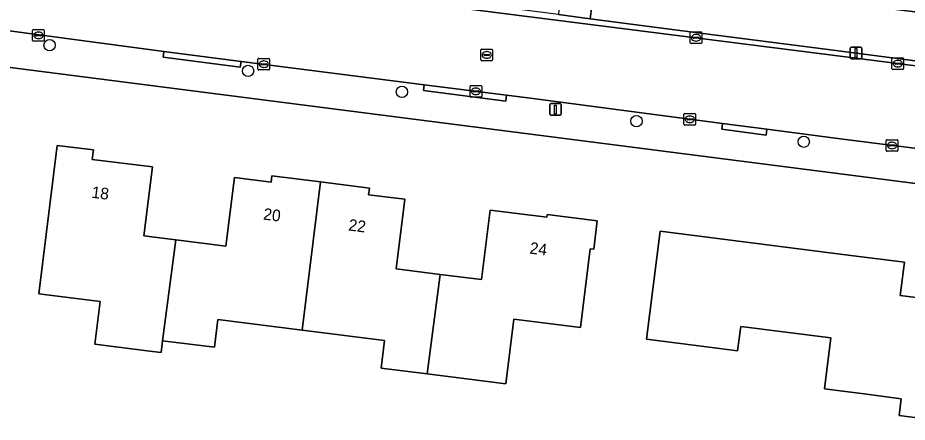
# Model space of a CAD drawing. Extents: x 162184 to 163154, y 385507 to 386516.
# Drawn here: x 162428.7 to 162505.3, y 386004.8 to 386039.6 of the extents above; entities that cross this region are included whole.
import ezdxf

# ---------------------------------------------------------------- set-up
doc = ezdxf.new("R2010")
doc.units = 0
for name, color, linetype in [('IMGEO_Boom', 7, 'Continuous'), ('IMGEO_Erf', 7, 'Continuous'), ('IMGEO_Groenvoorziening', 7, 'Continuous'), ('IMGEO_Kolk', 7, 'Continuous'), ('IMGEO_Lichtmast', 7, 'Continuous'), ('IMGEO_Pand', 7, 'Continuous'), ('IMGEO_Pand_nummerreeks', 7, 'Continuous'), ('IMGEO_Rijbaan_lokaal_open', 7, 'Continuous'), ('IMGEO_Rioolput', 7, 'Continuous'), ('IMGEO_Voetpad_open', 7, 'Continuous')]:
    doc.layers.add(name, color=color, linetype=linetype)

msp = doc.modelspace()

# ---------------------------------------------------------------- linework, layer by layer
at = {"layer": 'IMGEO_Boom'}
for centre in [(162431.465, 386037.28), (162448.562, 386035.061), (162461.812, 386033.263), (162482.006, 386030.738), (162496.412, 386028.965)]:
    msp.add_circle(centre, 0.489, dxfattribs=at)
at = {"layer": 'IMGEO_Erf'}
msp.add_lwpolyline([(162525.924, 386022.81), (162500, 386026.135), (162427.629, 386035.417), (162425.539, 386035.686)], dxfattribs=at)
for points in [[(162460.01, 386009.473), (162460.309, 386011.858), (162453.216, 386012.746), (162445.967, 386013.653), (162445.67, 386011.281), (162441.428, 386011.812), (162441.194, 386011.841), (162441.062, 386010.827), (162440.334, 386010.918), (162435.372, 386011.539), (162435.833, 386015.225), (162430.533, 386015.888), (162432.13, 386028.648), (162435.248, 386028.258), (162435.146, 386027.444), (162440.321, 386026.796), (162439.579, 386020.867), (162442.326, 386020.523), (162446.65, 386019.982), (162447.39, 386025.892), (162450.55, 386025.497), (162450.617, 386026.031), (162454.812, 386025.506), (162459.01, 386024.981), (162458.938, 386024.405), (162462.073, 386024.012), (162461.324, 386018.024), (162465.103, 386017.551), (162468.651, 386017.107), (162469.398, 386023.072), (162474.278, 386022.461), (162474.307, 386022.692), (162478.628, 386022.151), (162478.323, 386019.72), (162478.029, 386019.756), (162477.179, 386012.966), (162471.45, 386013.683), (162470.755, 386008.129), (162463.97, 386008.978)], [(162487.146, 386011.422), (162482.869, 386011.966), (162484.05, 386021.266), (162488.327, 386020.722), (162500, 386019.239), (162505.081, 386018.594), (162504.718, 386015.737), (162510.043, 386015.061), (162510.098, 386015.499), (162510.407, 386015.46), (162509.879, 386011.295), (162510.329, 386011.238), (162510.206, 386010.267), (162509.786, 386010.32), (162509.088, 386004.827), (162504.625, 386005.394), (162504.81, 386006.851), (162501.605, 386007.258), (162500, 386007.462), (162498.195, 386007.691), (162498.753, 386012.082), (162490.99, 386013.068), (162490.723, 386010.967)]]:
    msp.add_lwpolyline(points, close=True, dxfattribs=at)
at = {"layer": 'IMGEO_Groenvoorziening'}
msp.add_lwpolyline([(162478.556, 386043.58), (162478.063, 386039.785), (162478.033, 386039.554), (162487.53, 386038.32), (162498.29, 386036.923), (162500.92, 386036.604), (162519.499, 386034.169), (162519.545, 386034.527), (162520.029, 386038.411)], close=True, dxfattribs=at)
at = {"layer": 'IMGEO_Kolk'}
for p, q in [((162430.006, 386037.695), (162430.006, 386038.547)), ((162430.081, 386038.621), (162430.933, 386038.621)), ((162430.265, 386038.115), (162430.265, 386038.127)), ((162430.703, 386038.078), (162430.305, 386038.078)), ((162430.308, 386038.164), (162430.706, 386038.164)), ((162430.494, 386038.401), (162430.519, 386038.401)), ((162430.749, 386038.127), (162430.749, 386038.115)), ((162431.007, 386038.547), (162431.007, 386037.695)), ((162486.639, 386037.49), (162486.639, 386038.342)), ((162486.714, 386038.416), (162487.566, 386038.416)), ((162486.941, 386037.959), (162487.339, 386037.959)), ((162487.127, 386038.196), (162487.152, 386038.196)), ((162487.64, 386038.342), (162487.64, 386037.49)), ((162430.933, 386037.621), (162430.081, 386037.621)), ((162430.517, 386037.841), (162430.492, 386037.841)), ((162487.566, 386037.416), (162486.714, 386037.416)), ((162486.898, 386037.91), (162486.898, 386037.922)), ((162487.336, 386037.873), (162486.938, 386037.873)), ((162487.15, 386037.636), (162487.125, 386037.636)), ((162487.382, 386037.922), (162487.382, 386037.91)), ((162449.409, 386035.217), (162449.409, 386036.069)), ((162449.484, 386036.143), (162450.336, 386036.143)), ((162449.668, 386035.637), (162449.668, 386035.649)), ((162449.711, 386035.686), (162450.109, 386035.686)), ((162449.897, 386035.923), (162449.922, 386035.923)), ((162450.152, 386035.649), (162450.152, 386035.637)), ((162450.41, 386036.069), (162450.41, 386035.217)), ((162504.014, 386035.264), (162504.014, 386036.116)), ((162504.089, 386036.19), (162504.941, 386036.19)), ((162504.273, 386035.684), (162504.273, 386035.696)), ((162504.711, 386035.647), (162504.313, 386035.647)), ((162504.316, 386035.733), (162504.714, 386035.733)), ((162504.502, 386035.97), (162504.527, 386035.97)), ((162504.757, 386035.696), (162504.757, 386035.684)), ((162505.015, 386036.116), (162505.015, 386035.264)), ((162450.336, 386035.143), (162449.484, 386035.143)), ((162450.106, 386035.6), (162449.708, 386035.6)), ((162449.92, 386035.363), (162449.895, 386035.363)), ((162504.941, 386035.19), (162504.089, 386035.19)), ((162504.525, 386035.41), (162504.5, 386035.41)), ((162467.678, 386032.88), (162467.678, 386033.732)), ((162467.753, 386033.806), (162468.605, 386033.806)), ((162467.98, 386033.349), (162468.378, 386033.349)), ((162468.166, 386033.586), (162468.191, 386033.586)), ((162468.679, 386033.732), (162468.679, 386032.88)), ((162468.605, 386032.806), (162467.753, 386032.806)), ((162467.937, 386033.3), (162467.937, 386033.312)), ((162468.375, 386033.263), (162467.977, 386033.263)), ((162468.189, 386033.026), (162468.164, 386033.026)), ((162468.421, 386033.312), (162468.421, 386033.3)), ((162486.1, 386030.476), (162486.1, 386031.328)), ((162486.175, 386031.402), (162487.027, 386031.402)), ((162486.588, 386031.182), (162486.613, 386031.182)), ((162487.101, 386031.328), (162487.101, 386030.476)), ((162487.027, 386030.402), (162486.175, 386030.402)), ((162486.359, 386030.896), (162486.359, 386030.908)), ((162486.797, 386030.859), (162486.399, 386030.859)), ((162486.402, 386030.945), (162486.8, 386030.945)), ((162486.611, 386030.622), (162486.586, 386030.622)), ((162486.843, 386030.908), (162486.843, 386030.896)), ((162503.52, 386028.218), (162503.52, 386029.07)), ((162503.595, 386029.144), (162504.447, 386029.144)), ((162504.008, 386028.924), (162504.033, 386028.924)), ((162504.521, 386029.07), (162504.521, 386028.218)), ((162504.447, 386028.144), (162503.595, 386028.144)), ((162503.779, 386028.638), (162503.779, 386028.65)), ((162504.217, 386028.601), (162503.819, 386028.601)), ((162503.822, 386028.687), (162504.22, 386028.687)), ((162504.031, 386028.364), (162504.006, 386028.364)), ((162504.263, 386028.65), (162504.263, 386028.638))]:
    msp.add_line(p, q, dxfattribs=at)
for points in [[(162430.006, 386037.695), (162430.006, 386038.547)], [(162430.081, 386038.621), (162430.933, 386038.621)], [(162431.007, 386038.547), (162431.007, 386037.695)], [(162486.639, 386037.49), (162486.639, 386038.342)], [(162486.714, 386038.416), (162487.566, 386038.416)], [(162487.64, 386038.342), (162487.64, 386037.49)], [(162430.933, 386037.621), (162430.081, 386037.621)], [(162487.566, 386037.416), (162486.714, 386037.416)], [(162449.409, 386035.217), (162449.409, 386036.069)], [(162449.484, 386036.143), (162450.336, 386036.143)], [(162450.41, 386036.069), (162450.41, 386035.217)], [(162504.014, 386035.264), (162504.014, 386036.116)], [(162504.089, 386036.19), (162504.941, 386036.19)], [(162505.015, 386036.116), (162505.015, 386035.264)], [(162450.336, 386035.143), (162449.484, 386035.143)], [(162504.941, 386035.19), (162504.089, 386035.19)], [(162467.678, 386032.88), (162467.678, 386033.732)], [(162467.753, 386033.806), (162468.605, 386033.806)], [(162468.679, 386033.732), (162468.679, 386032.88)], [(162468.605, 386032.806), (162467.753, 386032.806)], [(162486.1, 386030.476), (162486.1, 386031.328)], [(162486.175, 386031.402), (162487.027, 386031.402)], [(162487.101, 386031.328), (162487.101, 386030.476)], [(162487.027, 386030.402), (162486.175, 386030.402)], [(162503.52, 386028.218), (162503.52, 386029.07)], [(162503.595, 386029.144), (162504.447, 386029.144)], [(162504.521, 386029.07), (162504.521, 386028.218)], [(162504.447, 386028.144), (162503.595, 386028.144)]]:
    msp.add_lwpolyline(points, dxfattribs=at)
for centre, radius, start, end in [((162430.083, 386038.545), 0.0765, 91.55205, 178.44795), ((162430.083, 386038.545), 0.0765, 91.55205, 178.44795), ((162430.305, 386038.124), 0.0403, 85.87752, 175.75265), ((162430.302, 386038.114), 0.0366, 178.93798, 274.71019), ((162430.706, 386038.121), 0.043, 264.86636, 352.45326), ((162430.71, 386038.126), 0.0386, 1.73085, 96.63898), ((162430.931, 386038.545), 0.0765, 1.55205, 88.44795), ((162430.931, 386038.545), 0.0765, 1.55205, 88.44795), ((162486.716, 386038.34), 0.0765, 91.55205, 178.44795), ((162486.716, 386038.34), 0.0765, 91.55205, 178.44795), ((162486.938, 386037.919), 0.0403, 85.87752, 175.75265), ((162487.343, 386037.921), 0.0386, 1.73085, 96.63898), ((162487.564, 386038.34), 0.0765, 1.55205, 88.44795), ((162487.564, 386038.34), 0.0765, 1.55205, 88.44795), ((162430.083, 386037.697), 0.0765, 181.55205, 268.44795), ((162430.083, 386037.697), 0.0765, 181.55205, 268.44795), ((162430.931, 386037.697), 0.0765, 271.55205, 358.44795), ((162430.931, 386037.697), 0.0765, 271.55205, 358.44795), ((162486.716, 386037.492), 0.0765, 181.55205, 268.44795), ((162486.716, 386037.492), 0.0765, 181.55205, 268.44795), ((162486.935, 386037.909), 0.0366, 178.93798, 274.71019), ((162487.339, 386037.916), 0.043, 264.86636, 352.45326), ((162487.564, 386037.492), 0.0765, 271.55205, 358.44795), ((162487.564, 386037.492), 0.0765, 271.55205, 358.44795), ((162449.486, 386036.067), 0.0765, 91.55205, 178.44795), ((162449.486, 386036.067), 0.0765, 91.55205, 178.44795), ((162449.708, 386035.646), 0.0403, 85.87752, 175.75265), ((162449.705, 386035.636), 0.0366, 178.93798, 274.71019), ((162450.109, 386035.643), 0.043, 264.86636, 352.45326), ((162450.113, 386035.648), 0.0386, 1.73085, 96.63898), ((162450.334, 386036.067), 0.0765, 1.55205, 88.44795), ((162450.334, 386036.067), 0.0765, 1.55205, 88.44795), ((162504.091, 386036.114), 0.0765, 91.55205, 178.44795), ((162504.091, 386036.114), 0.0765, 91.55205, 178.44795), ((162504.313, 386035.693), 0.0403, 85.87752, 175.75265), ((162504.31, 386035.683), 0.0366, 178.93798, 274.71019), ((162504.714, 386035.69), 0.043, 264.86636, 352.45326), ((162504.718, 386035.695), 0.0386, 1.73085, 96.63898), ((162504.939, 386036.114), 0.0765, 1.55205, 88.44795), ((162504.939, 386036.114), 0.0765, 1.55205, 88.44795), ((162449.486, 386035.219), 0.0765, 181.55205, 268.44795), ((162449.486, 386035.219), 0.0765, 181.55205, 268.44795), ((162450.334, 386035.219), 0.0765, 271.55205, 358.44795), ((162450.334, 386035.219), 0.0765, 271.55205, 358.44795), ((162504.091, 386035.266), 0.0765, 181.55205, 268.44795), ((162504.091, 386035.266), 0.0765, 181.55205, 268.44795), ((162504.939, 386035.266), 0.0765, 271.55205, 358.44795), ((162504.939, 386035.266), 0.0765, 271.55205, 358.44795), ((162467.755, 386033.73), 0.0765, 91.55205, 178.44795), ((162467.755, 386033.73), 0.0765, 91.55205, 178.44795), ((162467.977, 386033.309), 0.0403, 85.87752, 175.75265), ((162468.382, 386033.311), 0.0386, 1.73085, 96.63898), ((162468.603, 386033.73), 0.0765, 1.55205, 88.44795), ((162468.603, 386033.73), 0.0765, 1.55205, 88.44795), ((162467.755, 386032.882), 0.0765, 181.55205, 268.44795), ((162467.755, 386032.882), 0.0765, 181.55205, 268.44795), ((162467.974, 386033.299), 0.0366, 178.93798, 274.71019), ((162468.378, 386033.306), 0.043, 264.86636, 352.45326), ((162468.603, 386032.882), 0.0765, 271.55205, 358.44795), ((162468.603, 386032.882), 0.0765, 271.55205, 358.44795), ((162486.177, 386031.326), 0.0765, 91.55205, 178.44795), ((162486.177, 386031.326), 0.0765, 91.55205, 178.44795), ((162487.025, 386031.326), 0.0765, 1.55205, 88.44795), ((162487.025, 386031.326), 0.0765, 1.55205, 88.44795), ((162486.177, 386030.478), 0.0765, 181.55205, 268.44795), ((162486.177, 386030.478), 0.0765, 181.55205, 268.44795), ((162486.399, 386030.905), 0.0403, 85.87752, 175.75265), ((162486.396, 386030.895), 0.0366, 178.93798, 274.71019), ((162486.8, 386030.902), 0.043, 264.86636, 352.45326), ((162486.804, 386030.907), 0.0386, 1.73085, 96.63898), ((162487.025, 386030.478), 0.0765, 271.55205, 358.44795), ((162487.025, 386030.478), 0.0765, 271.55205, 358.44795), ((162503.597, 386029.068), 0.0765, 91.55205, 178.44795), ((162503.597, 386029.068), 0.0765, 91.55205, 178.44795), ((162504.445, 386029.068), 0.0765, 1.55205, 88.44795), ((162504.445, 386029.068), 0.0765, 1.55205, 88.44795), ((162503.597, 386028.22), 0.0765, 181.55205, 268.44795), ((162503.597, 386028.22), 0.0765, 181.55205, 268.44795), ((162503.819, 386028.647), 0.0403, 85.87752, 175.75265), ((162503.816, 386028.637), 0.0366, 178.93798, 274.71019), ((162504.22, 386028.644), 0.043, 264.86636, 352.45326), ((162504.224, 386028.649), 0.0386, 1.73085, 96.63898), ((162504.445, 386028.22), 0.0765, 271.55205, 358.44795), ((162504.445, 386028.22), 0.0765, 271.55205, 358.44795)]:
    msp.add_arc(centre, radius, start, end, dxfattribs=at)
for centre, major_axis, ratio, start_param, end_param in [((162430.493, 386038.121), (-0.387, 0.002), 0.722429, 4.712389, 7.853982), ((162430.518, 386038.121), (-0.39, 0.002), 0.717154, 1.570796, 4.712389), ((162487.126, 386037.916), (-0.387, 0.002), 0.722429, 4.712389, 7.853982), ((162487.151, 386037.916), (-0.39, 0.002), 0.717154, 1.570796, 4.712389), ((162449.896, 386035.643), (-0.387, 0.002), 0.722429, 4.712389, 7.853982), ((162449.921, 386035.643), (-0.39, 0.002), 0.717154, 1.570796, 4.712389), ((162504.501, 386035.69), (-0.387, 0.002), 0.722429, 4.712389, 7.853982), ((162504.526, 386035.69), (-0.39, 0.002), 0.717154, 1.570796, 4.712389), ((162468.165, 386033.306), (-0.387, 0.002), 0.722429, 4.712389, 7.853982), ((162468.19, 386033.306), (-0.39, 0.002), 0.717154, 1.570796, 4.712389), ((162486.587, 386030.902), (-0.387, 0.002), 0.722429, 4.712389, 7.853982), ((162486.612, 386030.902), (-0.39, 0.002), 0.717154, 1.570796, 4.712389), ((162504.007, 386028.644), (-0.387, 0.002), 0.722429, 4.712389, 7.853982), ((162504.032, 386028.644), (-0.39, 0.002), 0.717154, 1.570796, 4.712389)]:
    msp.add_ellipse(centre, major_axis=major_axis, ratio=ratio, start_param=start_param, end_param=end_param, dxfattribs=at)
at = {"layer": 'IMGEO_Lichtmast'}
for p, q in [((162500.425, 386036.204), (162500.425, 386037.004)), ((162500.425, 386037.004), (162500.425, 386036.204)), ((162500.525, 386037.104), (162501.315, 386037.104)), ((162501.315, 386037.104), (162500.525, 386037.104)), ((162501.415, 386037.004), (162501.415, 386036.204)), ((162501.415, 386036.204), (162501.415, 386037.004)), ((162501.315, 386036.104), (162500.525, 386036.104)), ((162500.525, 386036.104), (162501.315, 386036.104)), ((162474.536, 386031.352), (162474.536, 386032.152)), ((162474.536, 386032.152), (162474.536, 386031.352)), ((162474.636, 386032.252), (162475.426, 386032.252)), ((162475.426, 386032.252), (162474.636, 386032.252)), ((162475.526, 386032.152), (162475.526, 386031.352)), ((162475.526, 386031.352), (162475.526, 386032.152)), ((162475.426, 386031.252), (162474.636, 386031.252)), ((162474.636, 386031.252), (162475.426, 386031.252))]:
    msp.add_line(p, q, dxfattribs=at)
for points in [[(162500.845, 386036.979), (162500.995, 386036.979), (162500.995, 386036.229), (162500.845, 386036.229), (162500.845, 386036.979)], [(162474.956, 386032.127), (162475.106, 386032.127), (162475.106, 386031.377), (162474.956, 386031.377), (162474.956, 386032.127)]]:
    msp.add_lwpolyline(points, dxfattribs=at)
for centre, start, end in [((162500.525, 386037.004), 90, 180), ((162500.525, 386037.004), 90, 180), ((162501.315, 386037.004), 0, 90), ((162501.315, 386037.004), 360, 90), ((162500.525, 386036.204), 180, 270), ((162500.525, 386036.204), 180, 270), ((162501.315, 386036.204), 270, 0), ((162501.315, 386036.204), 270, 0), ((162474.636, 386032.152), 90, 180), ((162474.636, 386032.152), 90, 180), ((162475.426, 386032.152), 0, 90), ((162475.426, 386032.152), 360, 90), ((162474.636, 386031.352), 180, 270), ((162474.636, 386031.352), 180, 270), ((162475.426, 386031.352), 270, 0), ((162475.426, 386031.352), 270, 0)]:
    msp.add_arc(centre, 0.1, start, end, dxfattribs=at)
at = {"layer": 'IMGEO_Pand'}
for points in [[(162442.326, 386020.523), (162439.579, 386020.867), (162440.321, 386026.796), (162435.146, 386027.444), (162435.248, 386028.258), (162432.13, 386028.648), (162430.533, 386015.888), (162435.833, 386015.225), (162435.372, 386011.539), (162440.334, 386010.918), (162441.062, 386010.827), (162441.194, 386011.841)], [(162454.812, 386025.506), (162450.617, 386026.031), (162450.55, 386025.497), (162447.39, 386025.892), (162446.65, 386019.982), (162442.326, 386020.523), (162441.194, 386011.841), (162441.428, 386011.812), (162445.67, 386011.281), (162445.967, 386013.653), (162453.216, 386012.746)], [(162465.103, 386017.551), (162461.324, 386018.024), (162462.073, 386024.012), (162458.938, 386024.405), (162459.01, 386024.981), (162454.812, 386025.506), (162453.216, 386012.746), (162460.309, 386011.858), (162460.01, 386009.473), (162463.97, 386008.978)], [(162463.97, 386008.978), (162470.755, 386008.129), (162471.45, 386013.683), (162477.179, 386012.966), (162478.029, 386019.756), (162478.323, 386019.72), (162478.628, 386022.151), (162474.307, 386022.692), (162474.278, 386022.461), (162469.398, 386023.072), (162468.651, 386017.107), (162465.103, 386017.551)], [(162487.146, 386011.422), (162490.723, 386010.967), (162490.99, 386013.068), (162498.753, 386012.082), (162498.195, 386007.691), (162500, 386007.462), (162501.605, 386007.258), (162504.81, 386006.851), (162504.625, 386005.394), (162509.088, 386004.827), (162509.786, 386010.32), (162510.206, 386010.267), (162510.329, 386011.238), (162509.879, 386011.295), (162510.407, 386015.46), (162510.098, 386015.499), (162510.043, 386015.061), (162504.718, 386015.737), (162505.081, 386018.594), (162500, 386019.239), (162488.327, 386020.722), (162484.05, 386021.266), (162482.869, 386011.966)]]:
    msp.add_lwpolyline(points, close=True, dxfattribs=at)
at = {"layer": 'IMGEO_Rijbaan_lokaal_open'}
for points in [[(162500, 386036.267), (162458.097, 386041.609), (162453.274, 386042.224), (162441.857, 386043.741), (162416.511, 386047), (162403.455, 386048.678), (162392.654, 386050.067), (162370.437, 386052.921), (162333.146, 386057.71), (162331.957, 386057.856)], [(162411.465, 386040.722), (162441.318, 386036.733), (162447.955, 386035.886), (162463.723, 386033.874), (162470.821, 386032.968), (162472.666, 386032.732), (162489.419, 386030.537), (162493.24, 386030.037), (162500, 386029.151), (162526.463, 386025.819)], [(162530.454, 386032.366), (162500, 386036.267)]]:
    msp.add_lwpolyline(points, dxfattribs=at)
at = {"layer": 'IMGEO_Rioolput'}
for p, q in [((162468.612, 386036.016), (162468.612, 386036.868)), ((162468.687, 386036.942), (162469.539, 386036.942)), ((162468.871, 386036.436), (162468.871, 386036.448)), ((162468.914, 386036.485), (162469.312, 386036.485)), ((162469.1, 386036.722), (162469.125, 386036.722)), ((162469.355, 386036.448), (162469.355, 386036.436)), ((162469.613, 386036.868), (162469.613, 386036.016)), ((162469.539, 386035.942), (162468.687, 386035.942)), ((162469.309, 386036.399), (162468.911, 386036.399)), ((162469.123, 386036.162), (162469.098, 386036.162))]:
    msp.add_line(p, q, dxfattribs=at)
for points in [[(162468.612, 386036.016), (162468.612, 386036.868)], [(162468.687, 386036.942), (162469.539, 386036.942)], [(162469.613, 386036.868), (162469.613, 386036.016)], [(162469.539, 386035.942), (162468.687, 386035.942)]]:
    msp.add_lwpolyline(points, dxfattribs=at)
for centre, radius, start, end in [((162468.689, 386036.866), 0.0765, 91.55205, 178.44795), ((162468.689, 386036.866), 0.0765, 91.55205, 178.44795), ((162468.911, 386036.445), 0.0403, 85.87752, 175.75265), ((162468.908, 386036.435), 0.0366, 178.93798, 274.71019), ((162469.312, 386036.442), 0.043, 264.86636, 352.45326), ((162469.316, 386036.447), 0.0386, 1.73085, 96.63898), ((162469.537, 386036.866), 0.0765, 1.55205, 88.44795), ((162469.537, 386036.866), 0.0765, 1.55205, 88.44795), ((162468.689, 386036.018), 0.0765, 181.55205, 268.44795), ((162468.689, 386036.018), 0.0765, 181.55205, 268.44795), ((162469.537, 386036.018), 0.0765, 271.55205, 358.44795), ((162469.537, 386036.018), 0.0765, 271.55205, 358.44795)]:
    msp.add_arc(centre, radius, start, end, dxfattribs=at)
for centre, major_axis, ratio, start_param, end_param in [((162469.099, 386036.442), (-0.387, 0.002), 0.722429, 4.712389, 7.853982), ((162469.124, 386036.442), (-0.39, 0.002), 0.717154, 1.570796, 4.712389)]:
    msp.add_ellipse(centre, major_axis=major_axis, ratio=ratio, start_param=start_param, end_param=end_param, dxfattribs=at)
at = {"layer": 'IMGEO_Voetpad_open'}
for points in [[(162522.542, 386041.382), (162520.412, 386041.654), (162500, 386044.328), (162481.339, 386046.773), (162478.571, 386047.142), (162475.618, 386047.518), (162472.641, 386047.895), (162458.436, 386049.702), (162458.011, 386046.211), (162475.809, 386043.954), (162475.336, 386040.252), (162475.292, 386039.909), (162478.033, 386039.554), (162478.063, 386039.785), (162478.556, 386043.58), (162520.029, 386038.411), (162519.545, 386034.527), (162519.499, 386034.169), (162521.616, 386033.939), (162521.653, 386034.242), (162522.13, 386038.154), (162531.826, 386036.993)], [(162472.666, 386032.732), (162470.821, 386032.968), (162470.758, 386032.473), (162463.66, 386033.381), (162463.723, 386033.874), (162447.955, 386035.886), (162447.892, 386035.399), (162441.255, 386036.248), (162441.318, 386036.733), (162411.465, 386040.722)], [(162406.905, 386039.376), (162407.997, 386037.698), (162416.778, 386036.549), (162425.425, 386035.708), (162425.539, 386035.686), (162427.629, 386035.417), (162500, 386026.135), (162525.924, 386022.81)], [(162526.463, 386025.819), (162500, 386029.151), (162493.24, 386030.037), (162493.175, 386029.536), (162489.354, 386030.037), (162489.419, 386030.537), (162472.666, 386032.732)]]:
    msp.add_lwpolyline(points, dxfattribs=at)
for points in [[(162500.92, 386036.604), (162498.29, 386036.923), (162487.53, 386038.32), (162478.033, 386039.554), (162475.292, 386039.909), (162458.164, 386042.118), (162458.097, 386041.609), (162500, 386036.267), (162530.454, 386032.366), (162531.037, 386032.79), (162525.455, 386033.429), (162521.616, 386033.939), (162519.499, 386034.169)], [(162441.318, 386036.733), (162441.255, 386036.248), (162447.892, 386035.399), (162447.955, 386035.886)], [(162470.821, 386032.968), (162463.723, 386033.874), (162463.66, 386033.381), (162470.758, 386032.473)], [(162493.24, 386030.037), (162489.419, 386030.537), (162489.354, 386030.037), (162493.175, 386029.536)]]:
    msp.add_lwpolyline(points, close=True, dxfattribs=at)

# ---------------------------------------------------------------- texts
at = {"layer": 'IMGEO_Pand_nummerreeks'}
for s, rotation, p in [('18', 352.86095, (162435.041, 386024.151)), ('20', 352.70625, (162449.827, 386022.273)), ('22', 352.70359, (162457.163, 386021.334)), ('24', 352.86342, (162472.771, 386019.344))]:
    msp.add_text(s, height=1, rotation=rotation, dxfattribs=at).set_placement(p)

doc.saveas('drawing.dxf')
